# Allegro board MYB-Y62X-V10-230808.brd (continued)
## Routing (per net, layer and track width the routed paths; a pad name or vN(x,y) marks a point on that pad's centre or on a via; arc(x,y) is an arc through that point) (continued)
LVDS0_I2C_SDA: length 5.6
  BOTTOM w0.152: R437.2 R449.2 17.62,39.27 16.46,38.1 J6.33
LVDS0_TP_PEN: length 7.3
  BOTTOM w0.152: JP2.2 23.99,39.5 22.49,38 R144.1 R143.2
LVDS1_CLKN: length 10.8
  TOP w0.13: U17.A4 18.99,74.37 18.96,74.33 18.43,74.33 17.95,74.8 16.81,74.8 15.79,73.79 12.36,73.79 12.01,74.14 12.01,74.42 12.18,74.59 J8.27
LVDS1_CLKP: length 10.8
  TOP w0.13: J8.28 11.09,74.59 12.23,73.46 15.93,73.46 16.95,74.48 17.82,74.48 18.29,74 18.96,74 18.99,73.97 U17.A3
LVDS1_D0N: length 11
  TOP w0.13: J8.19 12.18,66.59 12.04,66.45 12.04,66.11 12.41,65.75 16.14,65.75 18.1,67.71 18.93,67.71 18.97,67.75 U15.A2
LVDS1_D0P: length 11
  TOP w0.13: J8.20 11.1,66.59 12.27,65.42 16.27,65.42 18.23,67.38 18.93,67.38 18.96,67.35 U15.A1
LVDS1_D1N: length 10.5
  TOP w0.13: J8.21 12.16,68.57 11.99,68.41 11.99,68.14 12.35,67.78 16.64,67.78 17.37,68.51 18.93,68.51 18.97,68.54 U15.A4
LVDS1_D1P: length 10.5
  TOP w0.13: J8.22 11.1,68.57 12.22,67.45 16.78,67.45 17.51,68.18 18.93,68.18 18.96,68.14 U15.A3
LVDS1_D2N: length 13
  TOP w0.13: J8.23 12.18,70.58 12.01,70.41 12.01,70.08 12.37,69.72 16.35,69.72 17.25,70.62 17.25,72.65 18.12,73.53 18.96,73.53 18.99,73.57 U17.A2
LVDS1_D2P: length 13
  TOP w0.13: J8.24 11.04,70.58 12.23,69.4 16.48,69.4 17.57,70.48 17.57,72.52 18.26,73.2 18.96,73.2 18.99,73.17 U17.A1
LVDS1_D3N: length 10.9
  TOP w0.13: J8.29 12.16,76.57 12,76.41 12,76.11 12.29,75.82 16,75.82 16.51,76.33 17.7,76.33 18.86,75.17 U17.A6
LVDS1_D3P: length 10.9
  TOP w0.13: U17.A5 18.8,74.77 17.56,76 16.64,76 16.13,75.49 12.15,75.49 11.07,76.57 J8.30
LVDS1_I2C_SCL: length 5
  BOTTOM w0.152: J5.34 16.27,66.43 17.42,65.28 R451.2 R467.2
LVDS1_I2C_SDA: length 4.7
  BOTTOM w0.152: R468.2 R492.2 17.64,66.93 J5.33
LVDS1_TP_PEN: length 8
  TOP w0.152: JP3.2 23.24,62.84 v2(21.93,64.15)
  BOTTOM w0.152: R146.1 R145.2 19.93,63.84 20.14,63.63 21.41,63.63 v2(21.93,64.15)
MCLK_12M: length 1.5
  TOP w0.152: R534.1 144.89,22.29 Y7.3
MIC_BIAS: length 4.2
  TOP w0.254: C130.1 48.35,17.18 R297.2 47.37,17.7 46.5,18.57 U27.16
MIC_IN: length 2.6
  TOP w0.254: C127.2 46.33,17.83 46,18.16 U27.15
MODULE_RESET_N: length 4.7
  BOTTOM w0.152: C200.1 TP26.1 44,48.4 J19.67
OSPI_CLK: length 12.5
  TOP w0.152: U55.B2 94.05,101.16 92.24,101.16 91.92,100.84 91.92,100.65 92.28,100.29 92.28,100.1 92.14,99.97 91.95,99.97 91.6,100.32 91.41,100.32 91.27,100.19 91.27,100 91.54,99.73 91.54,99.54 91.41,99.41 91.22,99.41 90.95,99.68 90.76,99.68 89.84,98.76 v2(89.84,96.27) R51.1
  BOTTOM w0.152: R51.1 v2(89.84,96.27)
OSPI_CS: length 8.3
  TOP w0.152: U55.C2 94.03,100.14 94.03,99.49 93.72,99.19 93.42,99.19 90.55,96.32 v2(90.55,96.24) 90.55,95.49 R54.1
  BOTTOM w0.152: R54.1 90.55,95.49 v2(90.55,96.24)
OSPI_DQ0: length 12.6
  TOP w0.152: U55.D3 96.06,99.16 96.06,98.25 96.53,97.78 98.13,97.78 98.47,98.12 98.47,98.93 98.62,99.09 99.11,99.09 99.26,98.93 99.26,97.71 98.78,97.23 97.2,97.23 96.95,96.98 v2(96.95,96.27) R52.1
  BOTTOM w0.152: R52.1 v2(96.95,96.27)
OSPI_DQ1: length 19.7
  TOP w0.152: R53.1 92.5,95.71 v2(91.94,96.27) ; v2(92.5,96.93) 93.29,96.93 94.03,97.66 94.03,98.81 94.55,99.33 U55.D2
  BOTTOM w0.152: R53.1 92.5,95.71 v2(91.94,96.27) 91.94,97.02 91.79,97.17 91.27,97.17 91.13,97.31 91.13,97.5 91.27,97.63 91.81,97.63 91.94,97.76 91.94,97.95 91.81,98.09 91.27,98.09 91.13,98.22 91.13,98.41 91.27,98.54 91.81,98.54 91.94,98.68 91.94,99.01 91.54,99.42 90.14,99.42 90.01,99.54 90.01,99.85 90.17,100 92.17,100 92.5,99.67 v2(92.5,96.93)
OSPI_DQ2: length 13.6
  TOP w0.152: U55.C4 97,101.12 98.07,101.12 98.2,101.25 98.2,101.62 98.33,101.75 98.55,101.75 98.68,101.62 98.68,101.25 98.82,101.12 99.09,101.12 99.25,101.28 99.25,101.59 99.39,101.73 99.58,101.73 99.71,101.59 99.71,101.25 99.84,101.12 100.33,101.12 101.04,100.41 101.04,97.82 v2(99.49,96.27) 99.49,95.44 R55.1
  BOTTOM w0.152: R55.1 99.61,96.14 v2(99.49,96.27)
OSPI_DQ3: length 11.3
  TOP w0.152: R56.1 v2(97.84,96.27) 97.84,96.65 97.99,96.8 98.88,96.8 100.15,98.07 100.15,98.42 100.01,98.55 99.88,98.55 99.74,98.69 99.74,98.88 99.88,99.01 100.01,99.01 100.15,99.14 100.15,99.36 99.59,99.92 98.57,99.92 97.84,99.19 97.03,99.19 U55.D4
  BOTTOM w0.152: R56.1 v2(97.84,96.27)
OSPI_DQ4: length 9.8
  TOP w0.152: R58.1 98.85,95.44 v2(98.85,96.27) 100.61,98.02 100.61,99.62 99.77,100.46 98.34,100.46 U55.D5
  BOTTOM w0.152: v2(98.85,96.27) 98.73,96.14 R58.1
OSPI_DQ5: length 19.5
  TOP w0.152: v2(96.36,96.52) 96.36,97.31 95.55,98.12 U55.E3 ; R59.1 96.06,95.5 v2(95.73,95.83)
  BOTTOM w0.152: v2(96.36,96.52) 95.47,96.52 95.32,96.67 95.32,97.16 96.16,97.99 96.16,99.36 96.31,99.52 98.68,99.52 98.83,99.67 98.83,100 98.68,100.15 95.91,100.15 95.47,99.72 95.47,98.15 94.79,97.46 94.79,96.34 95.3,95.83 v2(95.73,95.83) 96.06,95.5 R59.1
OSPI_DQ6: length 18.6
  TOP w0.152: v2(93.14,96.04) 93.14,95.56 R60.1 ; v2(94.12,96.99) 94.4,96.99 94.55,97.14 U55.E2
  BOTTOM w0.152: v2(94.12,96.99) 94.33,97.21 94.33,97.66 94.99,98.32 94.99,100.51 95.14,100.66 95.47,100.66 95.63,100.81 95.63,101.65 95.5,101.78 95.17,101.78 95.02,101.63 95.02,101.33 94.87,101.18 94.56,101.18 94.41,101.03 94.41,99.29 94.23,99.11 93.11,99.11 92.96,98.96 92.96,98.71 93.09,98.58 93.8,98.58 93.95,98.42 93.95,98.07 93.82,97.94 93.27,97.94 93.14,97.8 v2(93.14,96.04) 93.14,95.56 R60.1
OSPI_DQ7: length 5.4
  TOP w0.152: R61.1 91.39,95.54 v2(91.39,96.22) 91.39,96.55 93.5,98.66 U55.E1
  BOTTOM w0.152: v2(91.39,96.22) 91.39,95.54 R61.1
OSPI_INTN: length 11.6
  TOP w0.152: R57.1 R64.2 101.52,101.4 100.25,102.66 U55.A5
OSPI_RSTN: length 17
  TOP w0.152: U8.4 91.35,113.34 R68.2 v2(91.29,112.39) ; U55.A4 v2(97.36,103.47)
  BOTTOM w0.152: v2(91.29,112.39) 92.25,112.39 92.88,111.76 95.04,111.76 97.36,109.44 v2(97.36,103.47)
PG_VDD_3V3: length 101.8
  TOP w0.305: v2(49.01,41.52) 50.41,40.12 U3.1 ; v2(78.74,98.12) 78.74,97.9 U4.8
  ART03 w0.254: v2(57.37,83.06) 57.37,87.33 56.69,88.01 56.69,91.95 61.13,96.39 66.29,96.39 68.58,98.68 70,98.68 70.76,99.44 72.21,99.44 73.91,97.74 76.73,97.74 77.11,98.12 v2(78.74,98.12)
  BOTTOM w0.305: v2(57.37,83.06) 49.65,83.06 47.85,81.25 47.85,80.09 49.45,78.49 51.74,78.49 54.86,75.36 54.86,62.84 57.98,59.72 57.98,51.64 51.28,44.93 51.28,42.37 50.43,41.52 v2(49.01,41.52)
  BOTTOM w0.381: v2(78.74,98.12) 78.28,97.66 R544.2 R21.2 R22.1
RFFE_VIO_1V8: length 3.4
  BOTTOM w0.152: TP25.1 43.5,48.91 J19.65
RS485_A1: length 9.3
  TOP w0.508: v1(133.71,111.44) 132.95,111.44 R271.1 131.68,110.17 R270.2
  BOTTOM w0.508: v1(133.71,111.44) D17.2 133.71,115.67 J13.8
RS485_A2: length 12.9
  TOP w0.508: v1(123.68,111.42) 120.87,111.42 R282.1 119.61,110.17 R281.2
  BOTTOM w0.508: v1(123.68,111.42) D15.2 122.03,113.22 121.01,114.24 J13.11
RS485_B1: length 8.7
  TOP w0.508: v1(129.01,111.57) 129.51,111.57 R271.2 130.79,110.29 R272.2
  BOTTOM w0.508: J13.9 129.01,116.56 D16.2 v1(129.01,111.57)
RS485_B2: length 8.8
  TOP w0.508: R284.2 118.73,110.29 R282.2 118.51,110.99 v1(119.23,111.72)
  BOTTOM w0.508: v1(119.23,111.72) D14.2 117.2,115.25 J13.12
RTC_I2C_SCL: length 3.4
  TOP w0.152: R453.2 v2(116.76,70.36) U40.2
  BOTTOM w0.152: R453.2 v2(116.76,70.36)
RTC_I2C_SDA: length 4.1
  TOP w0.152: U40.13 v2(127.94,70.36) R493.2
  BOTTOM w0.152: R493.2 v2(127.94,70.36)
SDX2AP_STATUS: length 16.4
  BOTTOM w0.152: J19.38 36.75,54.36 35.86,53.47 32.15,53.47 31.67,52.98 31.67,46.41 R342.2
SEL_XDS110_INV: length 23.8
  TOP w0.152: v2(161.59,83.54) 164.62,83.54 165.4,84.33 168.65,84.33 169.29,84.96 J4.8 ; U12.2 155.62,85.09 155.94,84.77 155.94,84.14 155.24,83.44 154.48,83.44 153.84,82.8 153.84,81.79 154.35,81.28 U13.2 v2(156,81.28)
  BOTTOM w0.152: v2(161.59,83.54) 158.27,83.54 v2(156,81.28)
SOC_CSI0_RXCLKN: length 114.1
  TOP w0.13: v2(78.06,41.02) 77.9,41.18 77.9,41.72 77.58,42.04 70.79,42.04 70.44,42.38 70.44,45.25 70.78,45.58 U43.47
  ART03 w0.109: v2(78.06,41.02) 77.9,41.18 77.9,43.61 79,44.7 88.23,44.7 89.4,43.54 93.78,43.54 94.62,44.38 100.12,44.38 102.03,42.47 108.37,42.47 109.26,41.58 125.15,41.58 136.83,53.27 146.17,53.27 146.5,52.93 147.47,52.93 148,53.47 152.75,53.47 152.9,53.31 153.19,53.31 153.34,53.47 156.72,53.47 157.02,53.77 157.02,54.24 v2(157.19,54.4)
  BOTTOM w0.13: J9.18 165.61,52.15 165.52,52.07 165.02,52.07 164.78,52.31 164.78,52.51 164.52,52.77 164.32,52.77 163.75,53.34 160.96,53.34 160.5,53.79 159.75,53.79 159.59,53.95 159.23,53.95 159.08,53.79 158.71,53.79 158.56,53.95 158.19,53.95 158.04,53.79 157.15,53.79 157.02,53.92 157.02,54.24 v2(157.19,54.4)
SOC_CSI0_RXCLKP: length 114.1
  TOP w0.13: U43.46 69.78,45.58 70.12,45.25 70.12,42.24 70.65,41.71 77.44,41.71 77.57,41.58 77.57,41.18 v2(77.4,41.02)
  ART03 w0.109: v2(156.52,54.4) 156.69,54.24 156.69,53.9 156.58,53.79 147.87,53.79 147.33,53.26 146.64,53.26 146.31,53.59 136.7,53.59 125.01,41.91 109.39,41.91 108.5,42.8 102.16,42.8 100.26,44.7 94.48,44.7 93.65,43.87 89.53,43.87 88.37,45.03 78.86,45.03 77.57,43.74 77.57,41.18 v2(77.4,41.02)
  BOTTOM w0.13: v2(156.52,54.4) 156.69,54.24 156.69,53.79 157.01,53.47 160.37,53.47 160.82,53.01 163.61,53.01 164.89,51.74 165.48,51.74 165.56,51.65 J9.17
SOC_CSI0_RXN0: length 114.3
  TOP w0.13: v2(73.61,42.67) 73.44,42.84 73.44,45.25 73.78,45.58 U43.50
  ART03 w0.109: v2(157.31,57.38) 157.15,57.21 157.15,56.94 156.84,56.64 150.71,56.64 150.41,56.95 142.85,56.95 141.78,55.88 135.89,55.88 135.11,55.1 134.47,55.1 134.36,54.99 134.36,54.63 134.06,54.33 133.57,54.33 133.27,54.63 133.27,54.99 133.16,55.1 132.82,55.1 131.78,54.05 131.78,53.9 132.23,53.44 132.23,53.01 131.89,52.67 131.46,52.67 131,53.12 130.85,53.12 130.69,52.97 130.69,52.81 131.23,52.28 131.23,51.86 130.88,51.51 130.45,51.51 129.92,52.04 129.77,52.04 121.47,43.74 111.93,43.74 109.51,46.15 103.29,46.15 102.81,46.64 90.6,46.64 89.68,47.55 85.88,47.55 84.89,46.56 75.18,46.56 73.44,44.82 73.44,42.84 v2(73.61,42.67)
  BOTTOM w0.13: J9.24 165.56,55.15 165.48,55.07 165.27,55.07 164.52,55.82 164.32,55.82 164.17,55.98 163.81,55.98 163.65,55.82 163.29,55.82 163.13,55.98 162.77,55.98 162.61,55.82 161.85,55.82 160.78,56.9 160.07,56.9 159.89,57.07 159.55,57.07 159.37,56.9 159.03,56.9 158.85,57.07 158.51,57.07 158.34,56.9 157.28,56.9 157.15,57.03 157.15,57.21 v2(157.31,57.38)
SOC_CSI0_RXN1: length 114
  TOP w0.13: U43.53 76.78,45.58 76.44,45.25 76.44,42.84 v2(76.61,42.67)
  ART03 w0.109: v2(157.31,56.06) 157.15,55.9 157.15,55.29 156.77,54.92 155.87,54.92 155.41,55.37 153.29,55.37 152.71,54.79 146.72,54.79 146.22,55.3 143.48,55.3 142.79,54.61 136.27,54.61 131.7,50.04 129.61,50.04 129.07,49.5 129.07,49.34 129.57,48.85 129.57,48.42 129.22,48.07 128.8,48.07 128.3,48.57 128.15,48.57 127.99,48.42 127.99,48.26 128.49,47.76 128.49,47.34 128.14,46.99 127.72,46.99 127.22,47.49 127.06,47.49 126.91,47.33 126.91,47.18 127.41,46.68 127.41,46.26 127.06,45.91 126.63,45.91 126.14,46.41 125.98,46.41 125.83,46.25 125.83,46.1 126.32,45.6 126.32,45.17 125.98,44.83 125.55,44.83 125.05,45.32 124.9,45.32 122.17,42.6 110.78,42.6 108.75,44.63 106.99,44.63 106.17,43.81 103.17,43.81 101.34,45.65 77.4,45.65 76.44,44.69 76.44,42.84 v2(76.61,42.67)
  BOTTOM w0.13: J9.21 165.25,53.65 165.16,53.57 164.89,53.57 164.23,54.23 164.1,54.23 163.95,54.38 163.58,54.38 163.43,54.23 161.72,54.23 161.2,54.75 161.2,55 160.96,55.24 160.7,55.24 160.45,55.5 159.97,55.5 159.82,55.65 159.45,55.65 159.3,55.5 158.93,55.5 158.78,55.65 158.42,55.65 158.26,55.5 157.3,55.5 157.17,55.63 157.17,55.92 v2(157.31,56.06)
SOC_CSI0_RXN2: length 114
  TOP w0.13: U43.56 79.78,45.58 79.44,45.25 79.44,42.08 v2(79.61,41.91)
  ART03 w0.109: v2(157.17,52.84) 157.01,52.67 157.01,52.32 156.71,52.02 152.16,52.02 151.93,52.25 150.55,52.25 150.14,51.84 146.21,51.84 146.1,51.73 146.1,50.97 145.8,50.67 145.31,50.67 145,50.97 145,51.73 144.9,51.84 144.17,51.84 144.06,51.73 144.06,50.97 143.76,50.67 143.27,50.67 142.96,50.97 142.96,51.73 142.86,51.84 142.26,51.84 142.15,51.73 142.15,50.39 141.85,50.09 141.36,50.09 141.06,50.39 141.06,51.73 140.95,51.84 140.73,51.84 140.62,51.73 140.62,50.39 140.32,50.09 139.83,50.09 139.53,50.39 139.53,51.73 139.42,51.84 139.2,51.84 139.1,51.73 139.1,50.39 138.79,50.09 138.3,50.09 138,50.39 138,51.73 137.89,51.84 137.54,51.84 126.34,40.64 106.26,40.64 105.78,41.13 101.67,41.13 100.43,42.37 88.3,42.37 87.49,43.18 79.89,43.18 79.44,42.74 79.44,42.08 v2(79.61,41.91)
  BOTTOM w0.152: J9.15 165.51,50.65 165.45,50.59 164.85,50.59 164.47,50.97 164.47,51.22 164.16,51.53 163.91,51.53 163.25,52.19 160.98,52.19 160.82,52.35 160.37,52.35 160.21,52.19 159.76,52.19 159.6,52.35 159.15,52.35 158.99,52.19 158.54,52.19 158.38,52.35 157.93,52.35 157.77,52.19 157.17,52.19 157.02,52.34 157.02,52.69 v2(157.17,52.84)
SOC_CSI0_RXN3: length 114.2
  TOP w0.13: v2(82.61,41.53) 82.44,41.7 82.44,45.25 82.78,45.58 U43.59
  ART03 w0.109: v2(156.54,51.42) 156.37,51.26 156.37,50.82 156.07,50.52 148.74,50.52 147.37,49.15 142.38,49.15 142.27,49.04 142.27,48.1 141.97,47.8 141.48,47.8 141.18,48.1 141.18,49.04 141.07,49.15 140.85,49.15 140.74,49.04 140.74,48.1 140.44,47.8 139.95,47.8 139.65,48.1 139.65,49.04 139.54,49.15 139.32,49.15 139.21,49.04 139.21,48.1 138.91,47.8 138.42,47.8 138.12,48.1 138.12,49.04 138.01,49.15 136.88,49.15 133.82,46.09 133.82,45.94 134.37,45.39 134.37,44.97 134.02,44.62 133.6,44.62 133.05,45.16 132.9,45.16 132.74,45.01 132.74,44.85 133.29,44.31 133.29,43.88 132.94,43.54 132.51,43.54 131.97,44.08 131.82,44.08 131.66,43.93 131.66,43.77 132.2,43.23 132.2,42.8 131.86,42.45 131.43,42.45 130.89,43 130.73,43 130.58,42.84 130.58,42.69 131.12,42.14 131.12,41.72 130.78,41.37 130.35,41.37 129.8,41.92 129.65,41.92 129.02,41.29 129.02,41.13 129.43,40.73 129.43,40.3 129.08,39.95 128.65,39.95 128.25,40.36 128.09,40.36 126.65,38.92 101.51,38.92 99.02,41.4 87.78,41.4 86.91,42.27 82.63,42.27 82.44,42.08 82.44,41.7 v2(82.61,41.53)
  BOTTOM w0.152: J9.12 164.89,49.15 164.38,49.66 163.37,49.66 162.89,50.13 162.89,50.36 162.58,50.68 162.35,50.68 162.15,50.88 161.71,50.88 161.56,51.03 161.1,51.03 160.95,50.88 160.49,50.88 160.34,51.03 159.88,51.03 159.73,50.88 159.28,50.88 159.12,51.03 158.67,51.03 158.51,50.88 158.02,50.88 157.87,51.03 157.41,51.03 157.26,50.88 156.54,50.88 156.38,51.03 156.38,51.27 v2(156.54,51.42)
SOC_CSI0_RXP0: length 114.3
  TOP w0.13: v2(72.95,42.67) 73.12,42.84 73.12,45.25 72.78,45.58 U43.49
  ART03 w0.109: v2(156.65,57.38) 156.82,57.21 156.82,57.08 156.71,56.97 150.85,56.97 150.54,57.28 142.71,57.28 141.64,56.21 135.76,56.21 134.97,55.42 134.33,55.42 134.03,55.12 134.03,54.77 133.92,54.66 133.71,54.66 133.6,54.77 133.6,55.12 133.3,55.42 132.69,55.42 131.45,54.19 131.45,53.76 131.9,53.3 131.9,53.15 131.75,52.99 131.6,52.99 131.14,53.45 130.71,53.45 130.37,53.1 130.37,52.68 130.9,52.15 130.9,51.99 130.74,51.84 130.59,51.84 130.06,52.37 129.63,52.37 121.33,44.07 112.06,44.07 109.65,46.48 103.42,46.48 102.94,46.96 90.73,46.96 89.82,47.88 85.74,47.88 84.75,46.89 75.04,46.89 73.12,44.96 73.12,42.84 v2(72.95,42.67)
  BOTTOM w0.13: J9.23 165.61,54.65 165.53,54.74 165.14,54.74 164.38,55.5 161.71,55.5 160.64,56.57 157.14,56.57 156.82,56.89 156.82,57.21 v2(156.65,57.38)
SOC_CSI0_RXP1: length 114.1
  TOP w0.13: v2(75.95,42.67) 76.12,42.84 76.12,45.25 75.78,45.58 U43.52
  ART03 w0.109: v2(156.65,56.06) 156.82,55.9 156.82,55.43 156.64,55.24 156,55.24 155.55,55.7 153.16,55.7 152.57,55.12 146.86,55.12 146.35,55.63 143.35,55.63 142.66,54.94 136.13,54.94 131.56,50.37 129.48,50.37 128.75,49.63 128.75,49.21 129.24,48.71 129.24,48.56 129.09,48.4 128.93,48.4 128.44,48.9 128.01,48.9 127.66,48.55 127.66,48.13 128.16,47.63 128.16,47.47 128.01,47.32 127.85,47.32 127.35,47.82 126.93,47.82 126.58,47.47 126.58,47.04 127.08,46.55 127.08,46.39 126.92,46.24 126.77,46.24 126.27,46.73 125.85,46.73 125.5,46.39 125.5,45.96 125.99,45.46 125.99,45.31 125.84,45.15 125.69,45.15 125.19,45.65 124.76,45.65 122.04,42.93 110.92,42.93 108.89,44.96 106.85,44.96 106.04,44.14 103.31,44.14 101.48,45.97 77.26,45.97 76.12,44.83 76.12,42.84 v2(75.95,42.67)
  BOTTOM w0.13: v2(156.65,56.06) 156.84,55.87 156.84,55.49 157.16,55.17 160.31,55.17 161.58,53.9 164.09,53.9 164.76,53.24 165.16,53.24 165.25,53.15 J9.20
SOC_CSI0_RXP2: length 114
  TOP w0.13: U43.55 78.78,45.58 79.12,45.25 79.12,42.08 v2(78.95,41.91)
  ART03 w0.109: v2(156.51,52.84) 156.68,52.67 156.68,52.46 156.57,52.35 152.29,52.35 152.07,52.58 150.41,52.58 150.01,52.17 146.07,52.17 145.77,51.87 145.77,51.11 145.66,51 145.44,51 145.33,51.11 145.33,51.87 145.03,52.17 144.03,52.17 143.73,51.87 143.73,51.11 143.62,51 143.4,51 143.29,51.11 143.29,51.87 142.99,52.17 142.13,52.17 141.83,51.87 141.83,50.53 141.72,50.42 141.5,50.42 141.39,50.53 141.39,51.87 141.09,52.17 140.6,52.17 140.3,51.87 140.3,50.53 140.19,50.42 139.97,50.42 139.86,50.53 139.86,51.87 139.56,52.17 139.07,52.17 138.77,51.87 138.77,50.53 138.66,50.42 138.44,50.42 138.33,50.53 138.33,51.87 138.03,52.17 137.4,52.17 126.2,40.97 106.4,40.97 105.91,41.45 101.81,41.45 100.56,42.7 88.44,42.7 87.63,43.51 79.75,43.51 79.12,42.87 79.12,42.08 v2(78.95,41.91)
  BOTTOM w0.152: J9.14 165.54,50.15 165.45,50.24 164.7,50.24 163.1,51.84 157.03,51.84 156.67,52.2 156.67,52.69 v2(156.51,52.84)
SOC_CSI0_RXP3: length 114.2
  TOP w0.13: U43.58 81.78,45.58 82.12,45.25 82.12,41.7 v2(81.95,41.53)
  ART03 w0.109: v2(155.88,51.42) 156.04,51.26 156.04,50.96 155.94,50.85 148.6,50.85 147.23,49.48 142.24,49.48 141.94,49.18 141.94,48.24 141.83,48.13 141.61,48.13 141.5,48.24 141.5,49.18 141.2,49.48 140.71,49.48 140.41,49.18 140.41,48.24 140.3,48.13 140.08,48.13 139.98,48.24 139.98,49.18 139.67,49.48 139.18,49.48 138.88,49.18 138.88,48.24 138.77,48.13 138.56,48.13 138.45,48.24 138.45,49.18 138.15,49.48 136.75,49.48 133.5,46.23 133.5,45.8 134.04,45.26 134.04,45.1 133.89,44.95 133.73,44.95 133.19,45.49 132.76,45.49 132.41,45.14 132.41,44.72 132.96,44.17 132.96,44.02 132.8,43.86 132.65,43.86 132.11,44.41 131.68,44.41 131.33,44.06 131.33,43.64 131.88,43.09 131.88,42.94 131.72,42.78 131.57,42.78 131.02,43.33 130.6,43.33 130.25,42.98 130.25,42.55 130.79,42.01 130.79,41.85 130.64,41.7 130.49,41.7 129.94,42.24 129.51,42.24 128.69,41.42 128.69,41 129.1,40.59 129.1,40.44 128.94,40.28 128.79,40.28 128.38,40.69 127.96,40.69 126.51,39.24 101.65,39.24 99.16,41.73 87.91,41.73 87.05,42.6 82.49,42.6 82.12,42.22 82.12,41.7 v2(81.95,41.53)
  BOTTOM w0.152: v2(155.88,51.42) 156.03,51.27 156.03,50.88 156.39,50.53 162,50.53 163.22,49.31 164.24,49.31 164.74,48.8 165.37,48.8 165.52,48.65 J9.11
SOC_EXT_REFCLK1: length 121.2
  TOP w0.152: v2(15.24,95.38) 15.24,96.09 15.23,96.1 R147.2 15.21,96.12 J7.4 ; U43.L22 v2(83.74,48.82)
  ART03 w0.152: v2(55.65,77.22) 55.65,90.83 v2(55.16,91.31) ; v2(63.34,47.19) 64.63,45.91 71.38,45.91 74.29,48.82 v2(83.74,48.82)
  BOTTOM w0.152: v2(55.16,91.31) 32.13,91.31 28.07,95.38 v2(15.24,95.38) ; v2(63.34,47.19) 62.91,47.62 62.91,48.82 64.79,50.7 64.79,58.55 65.02,58.78 65.02,68.17 64.28,68.91 64.28,70.56 57.63,77.22 v2(55.65,77.22)
SOC_EXTINT_GPIO1_31: length 126.9
  TOP w0.152: v2(118.92,82.68) 125.17,76.43 135.05,76.43 136.25,75.23 R498.2 139.1,70.87 U42.1 ; U43.42 v2(63.47,48.33)
  ART03 w0.152: v2(69.9,87.25) 71.24,88.6 79.19,88.6 80.18,89.59 98.4,89.59 98.52,89.71 103.4,89.71 108.1,85.01 108.1,84.28 109.19,83.19 116.94,83.19 117.45,82.68 v2(118.92,82.68)
  BOTTOM w0.152: v2(63.47,48.33) 65.32,50.19 65.32,58.29 67.23,60.2 67.23,72.64 65.25,74.63 65.25,78.69 66.47,79.91 66.47,86.11 67.61,87.25 v2(69.9,87.25)
SOC_GPMC0_AD0/BOOTMODE00: length 92.7
  TOP w0.152: U43.118 108.61,83.33 113.97,77.98 114.6,77.98 v2(115.24,78.61) ; v2(163.52,48.13) 162.12,48.13 161.96,47.98 R206.1 165.72,47.24 J11.6
  ART03 w0.152: v2(163.52,48.13) 163.52,48.1 164.05,47.57 165.1,47.57 165.53,48.01 165.53,61.96 160.43,67.06 151.18,67.06 150.8,66.67 139.62,66.67 137.46,68.83 137.46,73.43 136.17,74.73 126.21,74.73 122.33,78.61 v2(115.24,78.61)
SOC_GPMC0_AD1/BOOTMODE01: length 93
  TOP w0.152: v2(163.49,50.16) 162.23,50.16 161.96,49.9 R207.1 165.74,49.28 J11.8 ; v2(106.85,77.41) 106.85,76 107.52,75.33 U43.110
  ART03 w0.152: v2(106.85,77.41) 120.28,77.41 121.33,76.36 121.33,76.14 121.14,75.95 121.14,75.74 121.35,75.52 121.57,75.52 121.76,75.71 121.97,75.71 122.19,75.49 122.19,75.28 122,75.09 122,74.87 122.21,74.66 122.43,74.66 122.62,74.85 122.84,74.85 124.58,73.1 130.74,73.1 130.9,72.95 130.9,72.26 131.05,72.11 131.35,72.11 131.51,72.26 131.51,72.95 131.66,73.1 131.96,73.1 132.12,72.95 132.12,72.26 132.27,72.11 132.57,72.11 132.73,72.26 132.73,72.95 132.88,73.1 133.18,73.1 133.33,72.95 133.33,72.26 133.49,72.11 133.79,72.11 133.94,72.26 133.94,72.95 134.1,73.1 134.9,73.1 135.91,72.09 135.91,68.3 139.06,65.15 151.68,65.15 152.07,65.53 159.86,65.53 164.13,61.26 164.13,57.15 163.49,56.51 v2(163.49,50.16)
SOC_GPMC0_AD2/BOOTMODE02: length 93
  TOP w0.152: J11.10 161.99,51.28 R208.1 v2(161.96,52.62) ; v2(111.68,73.91) 109.26,76.33 U43.111
  ART03 w0.152: v2(111.68,73.91) 110.49,73.91 110.23,73.66 110.23,72.83 110.38,72.67 111.45,72.67 111.6,72.52 111.6,72.22 111.45,72.06 110.38,72.06 110.23,71.91 110.23,71.61 110.38,71.46 111.45,71.46 111.6,71.3 111.6,71 111.45,70.85 110.38,70.85 110.23,70.69 110.23,70.39 110.38,70.24 111.45,70.24 111.6,70.08 111.6,69.78 111.45,69.63 110.38,69.63 110.23,69.47 110.23,69.01 110.38,68.86 124.96,68.86 127.2,66.62 130.7,66.62 130.96,66.37 130.96,66.16 130.58,65.77 130.58,65.56 130.79,65.34 131.01,65.34 131.39,65.72 131.6,65.72 131.82,65.51 131.82,65.29 131.44,64.91 131.44,64.7 131.66,64.48 131.87,64.48 132.25,64.86 132.47,64.86 132.68,64.65 132.68,64.43 132.3,64.05 132.3,63.83 132.52,63.62 132.73,63.62 133.11,64 133.33,64 133.55,63.78 133.55,63.57 133.16,63.19 133.16,62.97 133.38,62.75 133.6,62.75 133.98,63.14 134.19,63.14 134.41,62.92 134.41,62.7 134.03,62.32 134.03,62.11 134.24,61.89 134.46,61.89 134.84,62.27 135.06,62.27 135.61,61.72 153.34,61.72 153.97,62.36 158.97,62.36 160.7,60.62 160.7,53.88 v2(161.96,52.62)
SOC_GPMC0_AD3/BOOTMODE03: length 92.9
  TOP w0.152: U43.114 108.93,79.33 112.82,75.44 v2(112.95,75.44) ; v2(161.97,54.74) 161.96,54.73 R209.1 162.02,53.29 J11.12
  ART03 w0.152: v2(161.97,54.74) 161.97,60.71 159.24,63.44 153.27,63.44 152.47,62.64 136.55,62.64 135.08,64.11 135.08,64.32 135.8,65.05 135.8,65.26 135.58,65.48 135.37,65.48 134.64,64.75 134.43,64.75 134.21,64.97 134.21,65.19 134.94,65.91 134.94,66.13 134.72,66.34 134.51,66.34 133.78,65.62 133.57,65.62 133.35,65.83 133.35,66.05 134.07,66.77 134.07,66.99 133.86,67.2 133.64,67.2 132.92,66.48 132.7,66.48 132.49,66.7 132.49,66.91 133.21,67.64 133.21,67.85 133,68.07 132.78,68.07 132.06,67.34 131.84,67.34 131.62,67.56 131.62,67.77 132.35,68.5 132.35,68.71 132.13,68.93 131.92,68.93 131.19,68.2 130.98,68.2 130.45,68.73 129.25,68.73 128.82,69.16 127.36,69.16 126.59,69.93 113.74,69.93 112.95,70.71 112.95,71.69 113.1,71.84 114.19,71.84 114.35,72 114.35,72.3 114.19,72.45 113.1,72.45 112.95,72.61 112.95,73.26 113.1,73.41 114.19,73.41 114.35,73.56 114.35,73.87 114.19,74.02 113.1,74.02 112.95,74.17 v2(112.95,75.44)
SOC_GPMC0_AD4/BOOTMODE04: length 93.9
  TOP w0.152: v2(106.35,76.33) 106.35,75.79 106.8,75.34 106.8,69.54 107.01,69.33 U43.104 ; J11.16 163.25,57.27 163.24,57.28 v2(163.11,57.28) 162.61,56.77 R210.1
  ART03 w0.152: v2(106.35,76.33) 114.04,76.33 114.7,75.67 117.85,75.67 118.27,75.25 118.27,75.03 117.57,74.33 117.57,74.12 117.79,73.9 118,73.9 118.7,74.6 118.92,74.6 119.13,74.38 119.13,74.17 118.44,73.47 118.44,73.26 118.65,73.04 118.87,73.04 119.57,73.74 119.78,73.74 120,73.52 120,73.31 119.3,72.61 119.3,72.39 119.51,72.18 119.73,72.18 120.43,72.88 120.64,72.88 120.86,72.66 120.86,72.44 120.16,71.75 120.16,71.53 120.38,71.31 120.59,71.31 121.29,72.01 121.51,72.01 121.81,71.7 121.81,71.25 122.04,71.02 122.69,71.02 122.85,71.17 122.85,71.73 123,71.88 123.3,71.88 123.46,71.73 123.46,71.17 123.61,71.02 123.91,71.02 124.07,71.17 124.07,71.73 124.22,71.88 124.52,71.88 124.68,71.73 124.68,71.17 124.83,71.02 125.13,71.02 125.29,71.17 125.29,71.73 125.44,71.88 125.74,71.88 125.89,71.73 125.89,71.17 126.05,71.02 131.75,71.02 132.19,70.57 132.41,70.57 132.84,71 133.06,71 133.27,70.79 133.27,70.57 132.84,70.14 132.84,69.92 138.63,64.14 152.19,64.14 152.57,64.52 159.43,64.52 163.11,60.83 v2(163.11,57.28)
SOC_GPMC0_AD5/BOOTMODE05: length 93
  TOP w0.152: v2(160.19,57.66) 161.81,57.66 161.96,57.81 R211.1 161.96,58.92 162.32,59.28 J11.18 ; U43.L37 v2(106.85,67.56)
  ART03 w0.152: v2(160.19,57.66) 160.19,59.05 158.03,61.21 154.48,61.21 154.1,60.83 133.78,60.83 131.36,63.25 130.36,63.25 130.21,63.4 130.21,63.96 130.06,64.11 129.75,64.11 129.6,63.96 129.6,63.4 129.45,63.25 129.14,63.25 128.99,63.4 128.99,63.96 128.84,64.11 128.53,64.11 128.38,63.96 128.38,63.4 128.23,63.25 125.15,63.25 124.99,63.4 124.99,63.86 124.84,64.01 124.54,64.01 124.39,63.86 124.39,63.4 124.23,63.25 123.93,63.25 123.78,63.4 123.78,64.06 123.62,64.21 123.32,64.21 123.17,64.06 123.17,63.4 123.01,63.25 122.71,63.25 122.56,63.4 122.56,64.06 122.4,64.21 122.1,64.21 121.95,64.06 121.95,63.4 121.79,63.25 121.49,63.25 121.34,63.4 121.34,64.06 121.18,64.21 120.88,64.21 120.73,64.06 120.73,63.4 120.58,63.25 120.27,63.25 120.12,63.4 120.12,64.06 119.27,64.9 119.27,67.01 118.72,67.56 118.17,67.56 118.02,67.41 118.02,66.55 117.86,66.4 117.56,66.4 117.41,66.55 117.41,67.41 117.25,67.56 116.95,67.56 116.8,67.41 116.8,66.55 116.64,66.4 116.34,66.4 116.19,66.55 116.19,67.41 116.03,67.56 112.47,67.56 112.31,67.41 112.31,66.22 112.16,66.07 111.86,66.07 111.7,66.22 111.7,67.41 111.55,67.56 111.25,67.56 111.09,67.41 111.09,66.22 110.94,66.07 110.64,66.07 110.48,66.22 110.48,67.41 110.33,67.56 110.03,67.56 109.88,67.41 109.88,66.22 109.72,66.07 109.42,66.07 109.27,66.22 109.27,67.41 109.11,67.56 108.81,67.56 108.66,67.41 108.66,66.22 108.5,66.07 108.2,66.07 108.05,66.22 108.05,67.41 107.89,67.56 v2(106.85,67.56)
SOC_GPMC0_AD6/BOOTMODE06: length 92.5
  TOP w0.152: J11.20 162.04,61.29 R212.1 161.96,61.73 161.84,61.85 v2(158.8,61.85) ; v2(106.85,68.33) 105.08,70.1 U43.L38
  ART03 w0.152: v2(158.8,61.85) 154.35,61.85 153.77,61.26 134.11,61.26 129.46,65.91 126.14,65.91 125.98,66.07 125.98,67.06 125.83,67.21 125.53,67.21 125.37,67.06 125.37,64.92 125.22,64.77 124.92,64.77 124.77,64.92 124.77,68.12 124.61,68.28 124.31,68.28 124.16,68.12 124.16,64.92 124,64.77 123.7,64.77 123.55,64.92 123.55,68.12 123.39,68.28 123.09,68.28 122.94,68.12 122.94,64.92 122.78,64.77 122.48,64.77 122.33,64.92 122.33,66.75 122.17,66.9 121.87,66.9 121.72,66.75 121.72,64.92 121.56,64.77 121.26,64.77 121.11,64.92 121.11,66.75 120.96,66.9 120.65,66.9 120.5,66.75 120.5,64.92 120.35,64.77 120.04,64.77 119.89,64.92 119.89,67.18 118.74,68.33 v2(106.85,68.33)
SOC_GPMC0_AD7/BOOTMODE07: length 92.8
  TOP w0.152: J11.22 161.99,63.27 R213.1 161.96,63.76 161.72,64.01 158.29,64.01 v2(154.86,60.58) ; U43.L36 v2(106.85,65.02)
  ART03 w0.152: v2(106.85,65.02) 106.85,64.58 107.01,64.43 108.17,64.43 108.33,64.28 108.33,63.97 108.17,63.82 107.44,63.82 107.29,63.67 107.29,62.89 107.44,62.74 109.32,62.74 109.48,62.89 109.48,65.2 109.63,65.35 109.93,65.35 110.09,65.2 110.09,62.89 110.24,62.74 110.54,62.74 110.7,62.89 110.7,65.2 110.85,65.35 111.15,65.35 111.3,65.2 111.3,62.89 111.46,62.74 111.76,62.74 111.91,62.89 111.91,65.2 112.07,65.35 112.59,65.35 112.75,65.2 112.75,63.14 112.9,62.99 113.2,62.99 113.36,63.14 113.36,65.2 113.51,65.35 117.95,65.35 119.63,63.68 119.63,62.18 119.78,62.03 120.08,62.03 120.24,62.18 120.24,62.59 120.39,62.74 120.69,62.74 120.85,62.59 120.85,62.18 121,62.03 121.3,62.03 121.45,62.18 121.45,62.59 121.61,62.74 121.91,62.74 122.06,62.59 122.06,62.18 122.22,62.03 122.52,62.03 122.67,62.18 122.67,62.59 122.83,62.74 123.31,62.74 123.46,62.59 123.46,62.18 123.61,62.03 123.91,62.03 124.07,62.18 124.07,62.59 124.22,62.74 124.52,62.74 124.68,62.59 124.68,62.18 124.83,62.03 125.13,62.03 125.29,62.18 125.29,62.53 125.44,62.69 131.03,62.69 134.03,59.69 138.88,59.69 139.52,60.33 154.61,60.33 v2(154.86,60.58)
SOC_GPMC0_ADVN_ALE: length 98.9
  TOP w0.152: v2(95.42,87.96) 95.5,87.88 U43.L48 ; v2(163.62,58.29) 167.92,58.29 168.22,58.6 168.22,58.88 168.62,59.28 J11.17
  ART03 w0.152: v2(163.62,58.29) 163.62,61.09 159.69,65.02 152.32,65.02 151.94,64.64 138.88,64.64 134.79,68.73 134.79,70.94 134.18,71.55 128.39,71.55 127.45,72.49 121.97,72.49 117.62,76.83 106.73,76.83 106.35,77.22 106.35,77.65 106.78,78.08 107.84,78.08 108.35,78.59 108.35,80.98 106.22,83.11 106.22,84.35 102.43,88.14 100.06,88.14 99.8,87.88 95.5,87.88 v2(95.42,87.96)
SOC_GPMC0_BE0N_CLE: length 70.3
  TOP w0.152: U43.L34 v2(106.85,59.94) ; v2(156.26,60.07) 158.54,62.36 167.43,62.36 168.34,63.27 J11.21
  ART03 w0.152: v2(106.85,59.94) 107.82,58.98 123.44,58.98 124.91,60.45 131.36,60.45 133.32,58.5 140.46,58.5 141.27,59.31 155.49,59.31 v2(156.26,60.07)
SOC_GPMC0_BE1N: length 216.9
  TOP w0.152: S3.4 S3.3 164.84,34.42 D49.2 C247.1 C248.1 R417.2 v2(162.16,30.86) ; U43.L39 v2(104.06,71.58)
  ART03 w0.152: v2(152.22,47.52) 151.58,48.16 148.41,48.16 147.24,46.99 146.48,46.99 141.91,42.42 141.91,21.84 139.62,19.56 126.39,19.56 125.71,20.23 123.33,20.23 120.06,23.5 80.64,23.5 v2(79.37,24.77) ; v2(104.06,71.58) 103.81,71.32 103.81,51.18 101.77,49.15 92.35,49.15 91.21,50.29 73.94,50.29 73.07,49.43 v2(73.07,48.29)
  BOTTOM w0.152: v2(152.22,47.52) 154.33,47.52 155.91,45.94 155.91,44.69 156.21,44.4 157.7,44.4 159.69,42.42 159.69,35.69 162.16,33.22 v2(162.16,30.86) ; v2(79.37,24.77) 77.52,26.62 77.52,27.03 73.05,31.5 73.05,34.95 71.17,36.83 71.17,45.31 73.07,47.22 v2(73.07,48.29)
SOC_GPMC0_CLK: length 92.6
  TOP w0.152: v2(114.09,78.61) 109.52,83.19 109.52,84.71 108.9,85.33 U43.120 ; v2(165.01,48.14) 165.02,48.13 168.12,48.13 168.99,47.27 J11.5
  ART03 w0.152: v2(114.09,78.61) 114.6,78.11 121.89,78.11 123.03,76.96 123.03,76.75 122.83,76.54 122.83,76.33 123.05,76.11 123.26,76.11 123.47,76.31 123.68,76.31 123.9,76.1 123.9,75.88 123.69,75.68 123.69,75.46 123.91,75.25 124.12,75.25 124.33,75.45 124.54,75.45 124.76,75.24 124.76,75.02 124.56,74.82 124.56,74.6 124.77,74.39 124.99,74.39 125.19,74.59 125.41,74.59 125.8,74.19 135.68,74.19 136.93,72.95 136.93,68.81 139.57,66.17 151.05,66.17 151.43,66.55 160.24,66.55 165.02,61.77 165.02,48.14 v2(165.01,48.14)
SOC_GPMC0_CSN0: length 99.7
  TOP w0.152: J11.7 168.88,49.27 167.99,50.16 v2(164.13,50.16) ; U43.L47 v2(99.51,88.42)
  ART03 w0.152: v2(99.51,88.42) 99.56,88.47 102.74,88.47 106.73,84.48 106.73,83.39 109.11,81 109.11,79.15 110.54,77.72 120.67,77.72 124.79,73.61 135.33,73.61 136.39,72.54 136.39,68.48 139.21,65.66 151.3,65.66 151.68,66.04 160.07,66.04 164.51,61.59 164.51,56.49 164.13,56.11 v2(164.13,50.16)
SOC_GPMC0_DIR: length 69.9
  TOP w0.152: U43.L33 v2(106.65,57.4) ; v2(158.92,58.8) 159.3,59.18 161.37,59.18 161.9,59.72 R572.1 167.53,60.33 168.5,61.29 J11.19
  ART03 w0.152: v2(158.92,58.8) 141.65,58.8 140.84,57.99 132.81,57.99 130.98,59.82 125.01,59.82 123.67,58.47 107.72,58.47 v2(106.65,57.4)
SOC_GPMC0_OEN_REN: length 82.2
  TOP w0.152: U43.L40 105.08,74.17 v2(106.22,74.17) ; v2(162.61,54.74) 163.62,54.74 164.13,54.23 167.97,54.23 168.91,53.29 J11.11
  ART03 w0.152: v2(106.22,74.17) 105.84,74.55 105.84,75.06 106.63,75.84 113.71,75.84 114.55,75.01 115.82,75.01 120.44,70.38 127.15,70.38 127.68,69.85 131.95,69.85 138.68,63.12 152.07,63.12 152.95,64.01 159.3,64.01 162.61,60.71 v2(162.61,54.74)
SOC_GPMC0_WAIT0: length 73.9
  TOP w0.152: U43.L35 v2(106.85,62.48) ; J11.15 168.42,57.27 167.53,56.39 163.88,56.39 162.99,55.5 R571.1 161.33,56.13 v2(160.19,56.13)
  ART03 w0.152: v2(106.85,62.48) 107.36,61.98 113.97,61.98 115.13,60.81 117.67,60.81 118.79,59.69 123.34,59.69 124.86,61.21 131.62,61.21 133.83,59 139.87,59 140.69,59.82 154.99,59.82 155.75,60.58 157.91,60.58 159.56,58.93 159.56,56.77 v2(160.19,56.13)
SOC_GPMC0_WAIT1: length 57.9
  TOP w0.152: U43.L32 105.58,56.39 v2(105.58,56.41) ; R269.1 v2(131.3,78.61)
  BOTTOM w0.152: v2(105.58,56.41) 105.58,69.88 113.31,77.6 130.28,77.6 v2(131.3,78.61)
SOC_GPMC0_WEN: length 87.4
  TOP w0.152: v2(162.61,52.62) 163.03,52.2 167.64,52.2 168.55,51.28 J11.9 ; U43.L42 105.89,78.44 105.89,75.26 v2(106.35,74.8)
  ART03 w0.152: v2(106.35,74.8) 111.81,74.8 112.19,74.42 112.19,70.15 112.93,69.41 126.19,69.41 127.02,68.58 128.44,68.58 129.03,68 130.2,68 136.01,62.18 152.9,62.18 153.59,62.87 159.18,62.87 161.34,60.71 161.34,54.23 162.61,52.96 v2(162.61,52.62)
SOC_GPMC0_WPN: length 43.7
  TOP w0.152: v2(134.35,79.12) 134.35,91.4 R268.1 ; U43.L41 v2(105.08,77.72)
  BOTTOM w0.152: v2(134.35,79.12) 132.33,79.12 131.82,79.63 106.98,79.63 v2(105.08,77.72)
SOC_I2C1_SCL: length 50.8
  TOP w0.152: v2(111.15,87.33) U43.122
  BOTTOM w0.152: R192.1 150.03,72.39 138.76,83.67 123.01,83.67 120.32,86.36 118.66,86.36 117.78,87.25 112.44,87.25 112.06,87.63 111.44,87.63 v2(111.15,87.33)
SOC_I2C1_SCL_R: length 3.7
  TOP w0.152: R461.2 v2(146.86,69.34) 146.62,69.59 U42.22
  BOTTOM w0.152: R461.2 v2(146.86,69.34)
SOC_I2C1_SDA: length 209.6
  TOP w0.152: U43.121 111.02,86.33 v2(111.81,87.12) ; v2(109.94,93.04) 108.64,94.34 v2(104.16,94.34) ; R141.1 v2(149.27,70.23)
  ART03 w0.152: v2(63.42,84.48) 63.64,84.48 64.69,85.53 64.69,88.04 69.83,93.19 69.83,95.06 70.89,96.11 76.5,96.11 77.52,97.13 79.65,97.13 81.12,98.6 85.72,98.6 88.9,95.43 100.99,95.43 102.08,94.34 v2(104.16,94.34) ; v2(111.81,87.12) 111.81,88.39 109.94,90.26 v2(109.94,93.04)
  BOTTOM w0.152: R449.1 22.53,39.27 24.66,41.4 29.36,41.4 31.87,43.92 48.66,43.92 57.35,52.6 57.35,59.31 54.15,62.51 54.15,75.29 51.66,77.77 49.25,77.77 47.29,79.73 47.29,81.64 50.14,84.48 v2(63.42,84.48) ; v2(149.27,70.23) 149.27,72.24 138.35,83.16 122.75,83.16 120.06,85.85 118.54,85.85 117.65,86.74 112.19,86.74 v2(111.81,87.12)
SOC_I2C1_SDA_R: length 3.6
  TOP w0.152: R141.2 v2(146.86,70.23) 144.95,70.23 U42.23
  BOTTOM w0.152: R141.2 v2(146.86,70.23)
SOC_JTAG_EMU0: length 113.2
  TOP w0.152: U43.160 70.78,93.95 v2(71.22,94.39) ; J4.13 v2(164.13,81.15)
  ART03 w0.152: v2(122.47,89.28) 119.43,86.23 111.02,86.23 105.08,92.18 102.56,92.18 100.28,94.46 84.86,94.46 84.17,93.78 71.83,93.78 v2(71.22,94.39)
  BOTTOM w0.152: v2(164.13,81.15) 164.74,81.76 164.74,87.2 162.05,89.89 153.18,89.89 152.45,89.15 147.49,89.15 146.6,88.27 123.49,88.27 v2(122.47,89.28)
SOC_JTAG_EMU1: length 106.6
  TOP w0.152: J4.14 169.21,81.15 168.58,81.79 v2(162.99,81.79) ; v2(81.2,90.42) 80.78,90.84 U43.150
  ART03 w0.152: v2(120.82,89.28) 118.21,86.66 111.22,86.66 105.25,92.63 102.79,92.63 100.48,94.95 v2(86.28,94.95)
  BOTTOM w0.152: v2(120.82,89.28) 121.59,89.28 123.11,87.76 146.99,87.76 147.87,88.65 152.7,88.65 153.41,89.35 158.57,89.35 160.73,87.2 160.73,86.28 162.99,84.02 v2(162.99,81.79) ; v2(81.2,90.42) 86.15,90.42 86.79,91.06 86.79,93.47 86.28,93.98 v2(86.28,94.95)
SOC_JTAG_TCK: length 104.1
  TOP w0.152: R104.2 v2(160,85.09) ; U43.6 65.03,84.33 66.47,85.78 66.47,88.39 67.48,89.41 72.18,89.41 v2(73.07,90.3)
  BOTTOM w0.152: v2(160,85.09) 158.22,86.87 154.73,86.87 153.08,85.22 123.49,85.22 120.82,87.88 119.68,87.88 119.05,88.52 113.46,88.52 112.44,89.53 106.35,89.53 105.84,90.04 99.49,90.04 98.6,89.15 74.21,89.15 v2(73.07,90.3)
SOC_JTAG_TDI: length 109.7
  TOP w0.152: v2(157.72,86.3) 159.56,88.14 164.13,88.14 164.77,87.5 J4.3 ; v2(71.74,90.23) 67.04,90.23 65.71,88.9 65.71,87.07 64.97,86.33 U43.4
  BOTTOM w0.152: v2(157.72,86.3) 157.15,85.72 155.11,85.72 153.56,84.18 123.26,84.18 120.57,86.87 119.05,86.87 118.22,87.69 112.63,87.69 111.68,88.65 105.56,88.65 105.18,89.03 99.55,89.03 98.91,88.39 73.58,88.39 v2(71.74,90.23)
SOC_JTAG_TDO: length 111.8
  TOP w0.152: v2(73.83,90.3) 72.56,89.03 67.74,89.03 66.98,88.27 66.98,85.39 64.92,83.33 U43.7 ; v2(162.35,84.07) 164.51,84.07 165.4,84.96 J4.7
  BOTTOM w0.152: v2(73.83,90.3) 74.6,89.53 98.44,89.53 99.46,90.55 106.16,90.55 106.68,90.03 112.84,90.03 113.95,88.92 119.28,88.92 119.93,88.27 121.2,88.27 123.74,85.72 152.74,85.72 154.4,87.38 158.44,87.38 161.74,84.07 v2(162.35,84.07)
SOC_JTAG_TMS: length 110.9
  TOP w0.152: v2(74.6,90.3) 72.94,88.65 68.12,88.65 67.48,88.01 67.48,84.84 64.98,82.33 U43.8 ; 166.88,88.77 159.43,88.77 v2(158.54,87.88)
  BOTTOM w0.152: v2(158.54,87.88) 154.18,87.88 153.57,87.27 148.66,87.27 147.62,86.23 124,86.23 121.46,88.77 120.19,88.77 119.43,89.53 116.25,89.53 115.74,90.04 113.71,90.04 112.7,91.06 99.43,91.06 98.28,89.92 74.98,89.92 v2(74.6,90.3)
SOC_JTAG_TRSTN: length 114.7
  TOP w0.152: v2(72.31,90.3) 72.31,90.17 71.93,89.79 67.23,89.79 66.09,88.65 66.09,86.44 64.98,85.33 U43.5 ; v2(156.26,86.36) 159.43,89.53 168.63,89.53 169.39,88.77 170.78,88.77
  BOTTOM w0.152: v2(156.26,86.36) 154.99,86.36 153.34,84.71 123.36,84.71 120.7,87.38 119.43,87.38 118.66,88.14 113.08,88.14 112.17,89.05 106.12,89.05 105.63,89.53 99.46,89.53 98.7,88.77 73.83,88.77 v2(72.31,90.3)
SOC_LVDS0_A0N: length 79.3
  TOP w0.13: v2(21.8,49.8) 21.77,49.8 21.64,49.93 21.64,54.48 20.85,55.26 20.54,55.26 20.5,55.3 U14.C2 ; v2(50.71,51.56) 50.54,51.73 50.54,74.74 55.47,79.67 63.69,79.67 64.03,79.33 U43.11
  ART03 w0.109: v2(50.71,51.56) 50.54,51.4 50.54,50.97 50.24,50.67 21.99,50.67 21.64,50.32 21.64,49.91 21.75,49.8 v2(21.8,49.8)
  BOTTOM w0.13: R118.1 20.07,50.55 21.3,50.55 21.62,50.23 21.62,49.98 v2(21.8,49.8)
SOC_LVDS0_A0P: length 78.8
  TOP w0.13: U43.10 64.03,80.33 63.69,80 55.33,80 50.21,74.88 50.21,51.73 v2(50.05,51.56) ; v2(21.14,49.8) 21.18,49.8 21.31,49.93 21.31,54.34 20.72,54.94 20.54,54.94 20.5,54.9 U14.C1
  ART03 w0.109: v2(50.05,51.56) 50.21,51.4 50.21,51.11 50.1,51 21.86,51 21.31,50.45 21.31,49.91 21.2,49.8 v2(21.14,49.8)
  BOTTOM w0.13: v2(21.14,49.8) 21.29,49.94 21.29,50.09 21.16,50.22 20.07,50.22 R110.1
SOC_LVDS0_A1N: length 82.7
  TOP w0.13: U14.C4 20.5,56.1 20.54,56.06 21.56,56.06 22.65,54.97 22.65,48.12 22.78,47.99 v2(22.82,47.99) ; U43.14 64.03,76.33 63.69,76.67 58.4,76.67 52.32,70.58 52.32,53.76 v2(52.48,53.59)
  ART03 w0.109: v2(22.82,47.99) 22.77,47.99 22.63,48.13 22.63,49.33 22.91,49.61 24.78,49.61 24.89,49.5 24.89,49.07 25.19,48.77 25.68,48.77 25.98,49.07 25.98,49.5 26.09,49.61 26.31,49.61 26.42,49.5 26.42,49.07 26.72,48.77 27.21,48.77 27.51,49.07 27.51,49.5 27.62,49.61 50.83,49.61 52.32,51.1 52.32,53.43 v2(52.48,53.59)
  BOTTOM w0.13: v2(22.82,47.99) 22.63,48.18 22.63,48.45 22.31,48.77 20.07,48.77 R113.1
SOC_LVDS0_A1P: length 82.1
  TOP w0.13: v2(22.16,47.99) 22.2,47.99 22.33,48.12 22.33,54.83 21.42,55.73 20.54,55.73 20.5,55.7 U14.C3 ; v2(51.82,53.59) 51.99,53.76 51.99,70.72 58.27,77 63.69,77 64.03,77.33 U43.13
  ART03 w0.109: v2(22.16,47.99) 22.19,47.99 22.3,48.1 22.3,49.46 22.77,49.93 24.91,49.93 25.21,49.63 25.21,49.2 25.32,49.1 25.54,49.1 25.65,49.2 25.65,49.63 25.95,49.93 26.44,49.93 26.74,49.63 26.74,49.2 26.85,49.1 27.07,49.1 27.18,49.2 27.18,49.63 27.48,49.93 50.69,49.93 51.99,51.23 51.99,53.43 v2(51.82,53.59)
  BOTTOM w0.13: v2(22.16,47.99) 22.3,48.14 22.3,48.31 22.18,48.44 20.07,48.44 R115.1
SOC_LVDS0_A2N: length 89.6
  TOP w0.13: U43.17 64.03,73.33 63.69,73.67 57.8,73.67 54.22,70.1 54.22,55.03 v2(54.39,54.86) ; v2(23.84,46.22) 23.8,46.22 23.67,46.34 23.67,58.75 21.46,60.96 20.51,60.96 20.47,61 U16.C2
  ART03 w0.109: v2(23.84,46.22) 23.78,46.22 23.67,46.33 23.67,47.07 23.9,47.3 29.69,47.3 29.99,47.6 29.99,47.82 30.1,47.93 30.32,47.93 30.43,47.82 30.43,47.6 30.73,47.3 31.39,47.3 31.7,47.6 31.7,48.48 31.8,48.59 32.02,48.59 32.13,48.48 32.13,47.6 32.43,47.3 33.12,47.3 34.01,48.18 52.15,48.18 54.22,50.26 54.22,54.7 v2(54.39,54.86)
  BOTTOM w0.13: v2(23.84,46.22) 23.65,46.4 23.65,46.67 23.33,46.99 20.07,46.99 R119.1
SOC_LVDS0_A2P: length 89
  TOP w0.13: v2(23.17,46.22) 23.21,46.22 23.34,46.34 23.34,58.61 21.32,60.63 20.51,60.63 20.47,60.6 U16.C1 ; U43.16 64.03,74.33 63.69,74 57.66,74 53.89,70.23 53.89,55.03 v2(53.73,54.86)
  ART03 w0.109: v2(23.17,46.22) 23.23,46.22 23.34,46.33 23.34,47.2 23.76,47.62 29.55,47.62 29.66,47.73 29.66,47.96 29.96,48.26 30.45,48.26 30.75,47.96 30.75,47.73 30.86,47.62 31.26,47.62 31.37,47.73 31.37,48.62 31.67,48.92 32.16,48.92 32.46,48.62 32.46,47.73 32.57,47.62 32.98,47.62 33.87,48.51 52.01,48.51 53.89,50.39 53.89,54.7 v2(53.73,54.86)
  BOTTOM w0.13: v2(23.17,46.22) 23.32,46.36 23.32,46.53 23.19,46.66 20.07,46.66 R121.1
SOC_LVDS0_A3N: length 96.5
  TOP w0.13: v2(25.87,42.44) 25.69,42.61 25.69,59.57 22.71,62.56 20.51,62.56 20.47,62.59 U16.C6 ; U43.20 64.03,70.33 63.69,70.67 57.34,70.67 55.87,69.21 55.87,56.68 v2(56.04,56.52)
  ART03 w0.109: v2(25.87,42.44) 25.7,42.6 25.7,44.04 25.96,44.3 33.63,44.3 35.06,45.72 53.17,45.72 57.45,50.01 57.45,53.72 55.87,55.3 55.87,56.35 v2(56.04,56.52)
  BOTTOM w0.13: v2(25.87,42.44) 25.7,42.6 25.7,43.11 25.38,43.44 20.07,43.44 R128.1
SOC_LVDS0_A3P: length 95.9
  TOP w0.13: v2(55.38,56.52) 55.55,56.68 55.55,69.34 57.2,71 63.69,71 64.03,71.33 U43.19 ; U16.C5 20.47,62.19 20.51,62.23 22.57,62.23 25.36,59.44 25.36,42.6 v2(25.21,42.44)
  ART03 w0.109: v2(25.21,42.44) 25.37,42.6 25.37,44.18 25.82,44.63 33.5,44.63 34.92,46.05 53.03,46.05 57.12,50.14 57.12,53.59 55.55,55.16 55.55,56.35 v2(55.38,56.52)
  BOTTOM w0.13: v2(25.21,42.44) 25.37,42.6 25.37,42.98 25.24,43.11 20.07,43.11 R130.1
SOC_LVDS0_CLK0N: length 92.9
  TOP w0.13: v2(24.87,44.46) 24.7,44.63 24.7,59.17 22.11,61.76 20.51,61.76 20.47,61.79 U16.C4 ; U43.23 64.03,67.33 63.69,67.67 58.78,67.67 57.45,66.34 57.45,56.13 55.93,54.6 55.93,53.51 v2(56.09,53.34)
  ART03 w0.109: v2(24.87,44.46) 24.7,44.63 24.7,46.07 24.89,46.25 25.43,46.25 25.54,46.14 25.54,45.54 25.84,45.24 26.33,45.24 26.63,45.54 26.63,46.14 26.74,46.25 28.17,46.25 28.28,46.14 28.28,45.51 28.58,45.21 29.07,45.21 29.38,45.51 29.38,46.14 29.48,46.25 29.7,46.25 29.81,46.14 29.81,45.51 30.11,45.21 30.6,45.21 30.9,45.51 30.9,46.14 31.01,46.25 31.23,46.25 31.34,46.14 31.34,45.51 31.64,45.21 32.13,45.21 32.43,45.51 32.43,46.14 32.54,46.25 33.66,46.25 34.22,46.81 52.58,46.81 55.93,50.16 55.93,51.19 55.63,51.49 55.35,51.49 55.24,51.6 55.24,51.82 55.35,51.93 55.63,51.93 55.93,52.23 55.93,53.17 v2(56.09,53.34)
  BOTTOM w0.13: R123.1 20.07,45.21 24.36,45.21 24.68,44.89 24.68,44.64 v2(24.87,44.46)
SOC_LVDS0_CLK0P: length 92.3
  TOP w0.13: v2(55.43,53.34) 55.6,53.51 55.6,54.74 57.12,56.26 57.12,66.47 58.65,68 63.69,68 64.03,68.33 U43.22 ; v2(24.21,44.46) 24.37,44.63 24.37,59.03 21.97,61.43 20.51,61.43 20.47,61.4 U16.C3
  ART03 w0.109: v2(24.21,44.46) 24.37,44.63 24.37,46.2 24.75,46.58 25.56,46.58 25.86,46.28 25.86,45.67 25.97,45.57 26.19,45.57 26.3,45.67 26.3,46.28 26.6,46.58 28.31,46.58 28.61,46.28 28.61,45.65 28.72,45.54 28.94,45.54 29.05,45.65 29.05,46.28 29.35,46.58 29.84,46.58 30.14,46.28 30.14,45.65 30.25,45.54 30.47,45.54 30.58,45.65 30.58,46.28 30.88,46.58 31.37,46.58 31.67,46.28 31.67,45.65 31.78,45.54 32,45.54 32.11,45.65 32.11,46.28 32.41,46.58 33.52,46.58 34.08,47.14 52.45,47.14 55.6,50.29 55.6,51.06 55.49,51.17 55.21,51.17 54.91,51.47 54.91,51.96 55.21,52.26 55.49,52.26 55.6,52.37 55.6,53.17 v2(55.43,53.34)
  BOTTOM w0.13: v2(24.21,44.46) 24.36,44.61 24.36,44.76 24.23,44.89 20.07,44.89 R125.1
SOC_LVDS1_A0N: length 77.3
  TOP w0.13: v2(60.97,65.59) 61.14,65.42 61.14,65.02 61.48,64.67 63.69,64.67 64.03,64.33 U43.26 ; v2(27.69,80.95) 27.86,80.78 27.86,73.02 22.54,67.71 20.54,67.71 20.5,67.75 U15.C2
  ART03 w0.109: v2(60.97,65.59) 61.14,65.75 61.14,66.59 60.37,67.36 56.05,67.36 55.39,68.02 55.39,68.44 55.82,68.88 55.82,69.03 55.67,69.19 55.51,69.19 55.08,68.75 54.65,68.75 54.31,69.1 54.31,69.53 54.74,69.96 54.74,70.12 54.59,70.27 54.43,70.27 54,69.84 53.57,69.84 46.14,77.27 28.77,77.27 27.86,78.17 27.86,80.78 v2(27.69,80.95)
  BOTTOM w0.13: v2(27.69,80.95) 27.85,80.79 27.85,80.39 27.72,80.27 19.18,80.27 R109.1
SOC_LVDS1_A0P: length 77.9
  TOP w0.13: v2(28.35,80.95) 28.19,80.78 28.19,72.89 22.68,67.38 20.54,67.38 20.5,67.35 U15.C1 ; v2(61.63,65.59) 61.46,65.42 61.46,65.15 61.62,65 63.69,65 64.03,65.33 U43.25
  ART03 w0.109: v2(28.35,80.95) 28.19,80.78 28.19,78.31 28.9,77.6 46.27,77.6 53.71,70.16 53.86,70.16 54.3,70.6 54.72,70.6 55.07,70.25 55.07,69.83 54.63,69.39 54.63,69.24 54.79,69.08 54.94,69.08 55.38,69.52 55.8,69.52 56.15,69.17 56.15,68.74 55.72,68.31 55.72,68.16 56.18,67.69 60.5,67.69 61.46,66.73 61.46,65.75 v2(61.63,65.59)
  BOTTOM w0.13: R111.1 19.18,79.94 27.85,79.94 28.17,80.26 28.17,80.77 v2(28.35,80.95)
SOC_LVDS1_A1N: length 74.2
  TOP w0.13: v2(61.02,62.56) 61.19,62.4 61.19,61.99 61.51,61.67 63.69,61.67 64.03,61.33 U43.29 ; U15.C4 20.5,68.54 20.54,68.51 21.79,68.51 26.72,73.44 26.72,79 v2(26.55,79.17)
  ART03 w0.109: v2(26.55,79.17) 26.72,79 26.72,76.75 27.34,76.13 45.67,76.13 56.07,65.73 56.49,65.73 56.93,66.17 57.09,66.17 57.24,66.01 57.24,65.86 56.8,65.42 56.8,64.99 57.15,64.64 57.57,64.64 58.02,65.08 58.17,65.08 58.33,64.93 58.33,64.78 57.88,64.33 57.88,63.91 58.45,63.35 61.08,63.35 61.19,63.24 61.19,62.73 v2(61.02,62.56)
  BOTTOM w0.13: v2(26.55,79.17) 26.72,79 26.72,78.49 26.59,78.36 19.18,78.36 R114.1
SOC_LVDS1_A1P: length 74.7
  TOP w0.13: v2(27.21,79.17) 27.04,79 27.04,73.3 21.92,68.18 20.54,68.18 20.5,68.14 U15.C3 ; v2(61.68,62.56) 61.51,62.4 61.51,62.13 61.64,62 63.69,62 64.03,62.33 U43.28
  ART03 w0.109: v2(61.68,62.56) 61.51,62.73 61.51,63.37 61.21,63.67 58.58,63.67 58.21,64.04 58.21,64.2 58.65,64.64 58.65,65.07 58.31,65.41 57.88,65.41 57.44,64.97 57.29,64.97 57.13,65.13 57.13,65.28 57.57,65.72 57.57,66.15 57.22,66.49 56.8,66.49 56.36,66.05 56.2,66.05 45.8,76.45 27.48,76.45 27.04,76.89 27.04,79 v2(27.21,79.17)
  BOTTOM w0.13: R116.1 19.18,78.03 26.72,78.03 27.04,78.35 27.04,79 v2(27.21,79.17)
SOC_LVDS1_A2N: length 69.1
  TOP w0.13: v2(61.02,59.67) 61.19,59.51 61.19,58.99 61.51,58.67 63.69,58.67 64.03,58.33 U43.32 ; U17.C2 20.47,73.57 20.51,73.53 21.13,73.53 21.64,73.03 24.48,73.03 25.45,74 25.45,76.84 v2(25.26,77.03)
  ART03 w0.109: v2(25.26,77.03) 25.45,76.84 25.45,75.71 26.17,74.98 45.2,74.98 46.39,73.8 46.39,73.64 45.87,73.12 45.87,72.7 46.21,72.35 46.64,72.35 47.16,72.87 47.31,72.87 47.47,72.71 47.47,72.56 46.95,72.04 46.95,71.62 47.3,71.27 47.72,71.27 48.24,71.79 48.39,71.79 58.84,61.34 60.88,61.34 61.19,61.03 61.19,59.84 v2(61.02,59.67)
  BOTTOM w0.13: R120.1 19.18,76.58 25.32,76.58 25.45,76.71 25.45,76.84 v2(25.26,77.03)
SOC_LVDS1_A2P: length 69.5
  TOP w0.13: v2(61.68,59.67) 61.51,59.51 61.51,59.13 61.64,59 63.69,59 64.03,59.33 U43.31 ; v2(25.92,77.03) 25.77,76.89 25.77,73.86 24.61,72.7 21.5,72.7 20.99,73.2 20.51,73.2 20.47,73.17 U17.C1
  ART03 w0.109: v2(61.68,59.67) 61.51,59.84 61.51,61.17 61.01,61.67 58.97,61.67 48.53,72.12 48.1,72.12 47.59,71.6 47.43,71.6 47.28,71.75 47.28,71.91 47.8,72.42 47.8,72.85 47.45,73.2 47.02,73.2 46.5,72.68 46.35,72.68 46.19,72.83 46.19,72.99 46.71,73.51 46.71,73.93 45.34,75.31 26.31,75.31 25.77,75.85 25.77,76.89 v2(25.92,77.03)
  BOTTOM w0.13: R122.1 19.18,76.25 25.45,76.25 25.77,76.58 25.77,76.89 v2(25.92,77.03)
SOC_LVDS1_A3N: length 64.4
  TOP w0.13: U43.35 64.03,55.33 63.69,55.67 61.51,55.67 61.19,55.99 61.19,56.4 v2(61.02,56.56) ; v2(23.89,75.69) 24.05,75.53 24.05,75.26 23.92,75.13 20.27,75.13 20.24,75.17 U17.C6
  ART03 w0.109: v2(61.02,56.56) 61.19,56.73 61.19,57.35 48.46,70.08 46.09,70.08 43.85,72.32 43.85,72.74 44.13,73.02 44.13,73.18 43.98,73.33 43.82,73.33 43.54,73.05 43.12,73.05 42.46,73.71 24.45,73.71 24.05,74.11 24.05,75.53 v2(23.89,75.69)
  BOTTOM w0.13: v2(23.89,75.69) 24.05,75.53 24.05,73.49 23.59,73.03 19.18,73.03 R129.1
SOC_LVDS1_A3P: length 65
  TOP w0.13: U17.C5 20.47,74.77 20.51,74.8 24.06,74.8 24.38,75.13 24.38,75.53 v2(24.55,75.69) ; U43.34 64.03,56.33 63.69,56 61.64,56 61.51,56.13 61.51,56.4 v2(61.68,56.56)
  ART03 w0.109: v2(24.55,75.69) 24.38,75.53 24.38,74.24 24.58,74.04 42.59,74.04 43.25,73.38 43.41,73.38 43.69,73.66 44.11,73.66 44.46,73.31 44.46,72.89 44.18,72.61 44.18,72.45 46.22,70.41 48.59,70.41 61.51,57.49 61.51,56.73 v2(61.68,56.56)
  BOTTOM w0.13: v2(24.55,75.69) 24.38,75.53 24.38,73.36 23.72,72.7 19.18,72.7 R131.1
SOC_LVDS1_CLK0N: length 63.5
  TOP w0.13: U17.C4 20.47,74.37 20.51,74.33 22.65,74.33 22.97,74.01 22.97,73.72 v2(23.14,73.55) ; v2(61.02,54.83) 61.19,54.67 61.19,52.99 61.51,52.67 63.69,52.67 64.03,52.33 U43.38
  ART03 w0.109: v2(61.02,54.83) 61.19,54.67 61.19,54.28 61.08,54.18 60.3,54.18 59.91,54.56 59.91,57.31 48.06,69.16 45.47,69.16 41.86,72.77 23.19,72.77 22.97,72.98 22.97,73.39 v2(23.14,73.55)
  BOTTOM w0.13: R124.1 19.18,74.8 22.52,74.8 22.97,74.35 22.97,73.72 v2(23.14,73.55)
SOC_LVDS1_CLK0P: length 62.9
  TOP w0.13: v2(22.48,73.55) 22.65,73.72 22.65,73.87 22.52,74 20.51,74 20.47,73.97 U17.C3 ; U43.37 64.03,53.33 63.69,53 61.64,53 61.51,53.13 61.51,54.67 v2(61.68,54.83)
  ART03 w0.109: v2(22.48,73.55) 22.65,73.39 22.65,72.85 23.05,72.44 41.73,72.44 45.33,68.84 47.92,68.84 59.58,57.18 59.58,54.43 60.16,53.85 61.21,53.85 61.51,54.15 61.51,54.67 v2(61.68,54.83)
  BOTTOM w0.13: v2(22.48,73.55) 22.65,73.72 22.65,74.22 22.39,74.48 19.18,74.48 R126.1
SOC_MCASP0_ACLKX: length 33.1
  TOP w0.152: U43.L13 v2(68.5,56.39) ; U54.4 v2(71.42,32.31)
  BOTTOM w0.152: v2(68.5,56.39) 68.5,54.74 69.01,54.23 69.01,44.45 65.07,40.51 65.07,36.96 66.72,35.31 70.53,35.31 71.42,34.42 v2(71.42,32.31)
SOC_MCASP0_AFSX: length 29
  TOP w0.152: U43.L14 v2(68.5,53.85) ; v2(70.91,34.26) U54.7
  BOTTOM w0.152: v2(68.5,53.85) 68.5,44.66 64.56,40.72 64.56,36.75 66.51,34.8 70.37,34.8 v2(70.91,34.26)
SOC_MCASP0_AXR0: length 25.5
  TOP w0.152: U43.L15 v2(67.36,52.32) ; U54.9 67.63,34.91 v2(68.25,34.29)
  BOTTOM w0.152: v2(67.36,52.32) 67.99,51.69 67.99,44.83 64.05,40.89 64.05,36.58 66.34,34.29 v2(68.25,34.29)
SOC_MCASP0_AXR1: length 23.6
  TOP w0.152: U54.12 v2(68.31,32.96) ; U43.L16 v2(67.48,49.78)
  BOTTOM w0.152: v2(67.48,49.78) 67.48,44.96 63.55,41.02 63.55,36.32 66.91,32.96 v2(68.31,32.96)
SOC_MCU_MCAN0_RX: length 91.3
  TOP w0.152: R257.1 v2(155.17,88.9) ; U43.L57 v2(74.72,87.88)
  ART03 w0.152: v2(74.72,87.88) 79.17,87.88 80.46,89.18 98.62,89.18 98.78,89.33 103.1,89.33 107.72,84.72 107.72,83.95 108.99,82.68 116.59,82.68 117.1,82.17 119.17,82.17 124.25,87.25 v2(125.14,87.25)
  BOTTOM w0.152: v2(125.14,87.25) 147.24,87.25 148.13,88.14 152.95,88.14 153.72,88.9 v2(155.17,88.9)
SOC_MCU_MCAN0_TX: length 88.4
  TOP w0.152: U43.L54 v2(80.18,87.88) ; R252.1 v2(157.71,88.9)
  ART03 w0.152: v2(80.18,87.88) 81.07,88.77 98.94,88.77 99.11,88.95 102.89,88.95 107.23,84.61 107.23,83.67 108.73,82.17 116.38,82.17 116.89,81.66 119.43,81.66 v2(124.51,86.74)
  BOTTOM w0.152: v2(124.51,86.74) 147.49,86.74 148.4,87.65 153.19,87.65 153.93,88.39 157.21,88.39 v2(157.71,88.9)
SOC_MCU_MCAN1_RX: length 44.1
  TOP w0.152: v2(89.58,99.31) 96.24,105.97 97.28,105.97 100.5,109.19 D53.2 ; v2(87.42,90.42) 86.91,89.92 79.17,89.92 78.66,89.41 U43.L55
  BOTTOM w0.152: v2(87.42,90.42) 87.3,90.55 87.3,98.35 88.26,99.31 v2(89.58,99.31)
